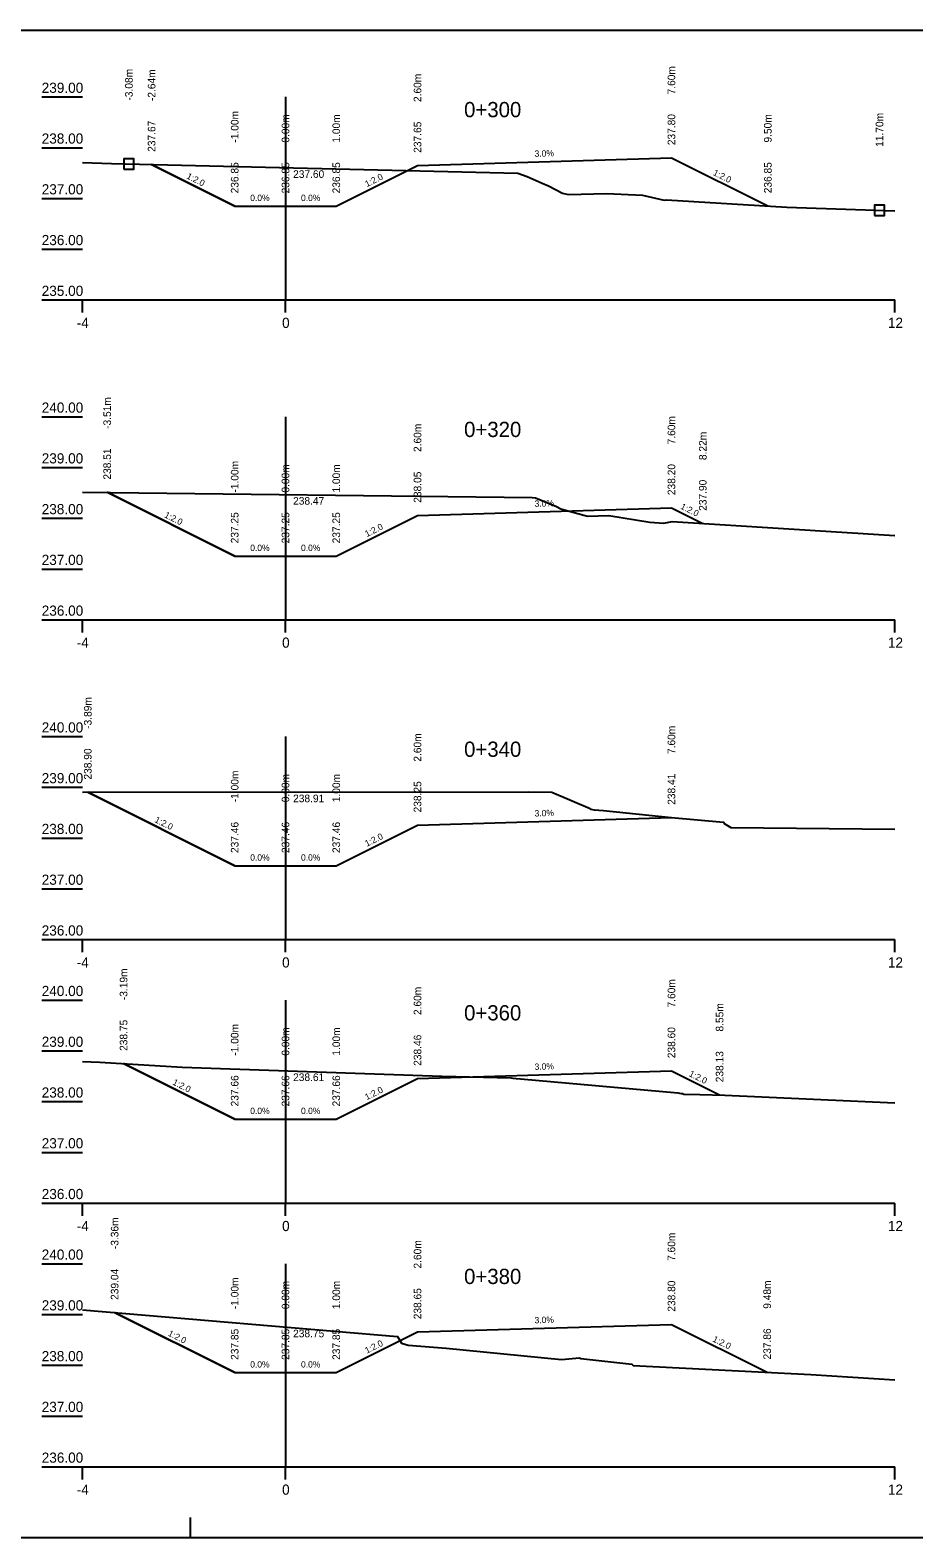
# Model space of a CAD drawing. Extents: x -578374 to -578229, y -1159997 to -1159967.
# Drawn here: x -578295.08 to -578277.68, y -1159996.88 to -1159967.18 of the extents above; entities that cross this region are included whole.
import ezdxf

# ---------------------------------------------------------------- set-up
doc = ezdxf.new("R2010")
doc.units = 0
for name, color, linetype in [('16', 7, 'Continuous'), ('21', 7, 'Continuous'), ('28', 7, 'Continuous'), ('59', 7, 'Continuous'), ('Body pricny rez', 7, 'Continuous'), ('Hranice_pozemku', 7, 'Continuous'), ('Popis pricneho profilu', 7, 'Continuous'), ('Rámy', 7, 'Continuous')]:
    doc.layers.add(name, color=color, linetype=linetype)

msp = doc.modelspace()

# ---------------------------------------------------------------- linework, layer by layer
for points in [[(-578292.693, -1159969.83), (-578291.057, -1159970.649), (-578290.057, -1159970.649), (-578289.057, -1159970.649), (-578287.457, -1159969.849), (-578282.457, -1159969.699), (-578280.559, -1159970.647)], [(-578289.057, -1159970.649), (-578287.457, -1159969.849), (-578282.457, -1159969.699)], [(-578282.457, -1159969.699), (-578280.559, -1159970.647)], [(-578294.057, -1159969.792), (-578293.48, -1159969.812), (-578285.481, -1159970.002), (-578285.299, -1159970.066), (-578285, -1159970.197), (-578284.877, -1159970.247), (-578284.599, -1159970.391), (-578284.489, -1159970.422), (-578283.726, -1159970.398), (-578283.025, -1159970.433), (-578282.599, -1159970.531), (-578282.553, -1159970.523), (-578280.182, -1159970.671), (-578278.057, -1159970.742)], [(-578291.057, -1159970.649), (-578292.693, -1159969.83)], [(-578291.057, -1159970.649), (-578290.057, -1159970.649), (-578289.057, -1159970.649)], [(-578280.559, -1159970.647), (-578280.56, -1159970.647), (-578280.559, -1159970.647), (-578280.56, -1159970.648), (-578280.559, -1159970.647), (-578280.559, -1159970.648), (-578280.559, -1159970.647), (-578280.559, -1159970.647)], [(-578294.057, -1159976.281), (-578285.202, -1159976.389), (-578285.133, -1159976.396), (-578284.72, -1159976.565), (-578284.635, -1159976.61), (-578284.111, -1159976.76), (-578283.69, -1159976.746), (-578282.885, -1159976.873), (-578282.609, -1159976.892), (-578282.444, -1159976.864), (-578278.057, -1159977.137)], [(-578293.568, -1159976.287), (-578291.057, -1159977.543), (-578290.057, -1159977.543), (-578289.057, -1159977.543), (-578287.457, -1159976.743), (-578282.457, -1159976.593), (-578281.84, -1159976.902)], [(-578291.057, -1159977.543), (-578293.568, -1159976.287)], [(-578289.057, -1159977.543), (-578287.457, -1159976.743), (-578282.457, -1159976.593)], [(-578282.457, -1159976.593), (-578281.84, -1159976.902)], [(-578281.84, -1159976.902), (-578281.84, -1159976.901), (-578281.84, -1159976.902), (-578281.84, -1159976.902), (-578281.84, -1159976.902), (-578281.839, -1159976.902), (-578281.84, -1159976.902), (-578281.839, -1159976.901)], [(-578291.057, -1159977.543), (-578290.057, -1159977.543), (-578289.057, -1159977.543)], [(-578294.057, -1159982.197), (-578285.267, -1159982.187), (-578284.821, -1159982.192), (-578284.814, -1159982.192), (-578284.06, -1159982.518), (-578284.049, -1159982.529), (-578283.981, -1159982.545), (-578283.794, -1159982.557), (-578282.457, -1159982.693), (-578281.43, -1159982.784), (-578281.417, -1159982.814), (-578281.289, -1159982.888), (-578278.057, -1159982.921)], [(-578293.95, -1159982.196), (-578291.057, -1159983.643), (-578290.057, -1159983.643), (-578289.057, -1159983.643), (-578287.457, -1159982.843), (-578282.457, -1159982.693)], [(-578291.057, -1159983.643), (-578293.95, -1159982.196)], [(-578289.057, -1159983.643), (-578287.457, -1159982.843), (-578282.457, -1159982.693)], [(-578291.057, -1159983.643), (-578290.057, -1159983.643), (-578289.057, -1159983.643)], [(-578294.057, -1159987.497), (-578293.714, -1159987.512), (-578292.092, -1159987.614), (-578286.979, -1159987.79), (-578285.612, -1159987.822), (-578285.579, -1159987.828), (-578285.512, -1159987.832), (-578285.431, -1159987.838), (-578282.334, -1159988.12), (-578282.267, -1159988.128), (-578282.241, -1159988.128), (-578282.216, -1159988.14), (-578282.215, -1159988.142), (-578282.207, -1159988.146), (-578281.895, -1159988.149), (-578281.404, -1159988.162), (-578278.057, -1159988.317)], [(-578293.245, -1159987.541), (-578291.057, -1159988.635), (-578290.057, -1159988.635), (-578289.057, -1159988.635), (-578287.457, -1159987.835), (-578282.457, -1159987.685), (-578281.509, -1159988.159)], [(-578291.057, -1159988.635), (-578293.245, -1159987.541)], [(-578289.057, -1159988.635), (-578287.457, -1159987.835), (-578282.457, -1159987.685)], [(-578282.457, -1159987.685), (-578281.509, -1159988.159)], [(-578281.509, -1159988.159), (-578281.51, -1159988.159), (-578281.509, -1159988.159), (-578281.51, -1159988.16), (-578281.509, -1159988.159), (-578281.509, -1159988.16), (-578281.509, -1159988.159), (-578281.509, -1159988.159)], [(-578291.057, -1159988.635), (-578290.057, -1159988.635), (-578289.057, -1159988.635)], [(-578294.057, -1159992.392), (-578287.852, -1159992.92), (-578287.771, -1159993.051), (-578287.64, -1159993.086), (-578286.894, -1159993.149), (-578284.619, -1159993.369), (-578284.265, -1159993.339), (-578284.24, -1159993.352), (-578283.234, -1159993.462), (-578283.209, -1159993.489), (-578279.714, -1159993.663), (-578278.057, -1159993.77)], [(-578293.421, -1159992.446), (-578291.057, -1159993.628), (-578290.057, -1159993.628), (-578289.057, -1159993.628), (-578287.457, -1159992.828), (-578282.457, -1159992.678), (-578280.572, -1159993.62)], [(-578291.057, -1159993.628), (-578293.421, -1159992.446)], [(-578289.057, -1159993.628), (-578287.457, -1159992.828), (-578282.457, -1159992.678)], [(-578282.457, -1159992.678), (-578280.572, -1159993.62)], [(-578291.057, -1159993.628), (-578290.057, -1159993.628), (-578289.057, -1159993.628)], [(-578280.572, -1159993.62), (-578280.573, -1159993.62), (-578280.572, -1159993.62), (-578280.573, -1159993.621), (-578280.572, -1159993.62), (-578280.572, -1159993.621), (-578280.572, -1159993.62), (-578280.572, -1159993.62)]]:
    msp.add_lwpolyline(points)
at = {"layer": '16'}
for p, q in [((-578294.057, -1159972.498), (-578278.057, -1159972.498)), ((-578294.057, -1159978.798), (-578278.057, -1159978.798)), ((-578294.057, -1159985.098), (-578278.057, -1159985.098)), ((-578294.057, -1159990.29), (-578278.057, -1159990.29)), ((-578294.057, -1159995.483), (-578278.057, -1159995.483))]:
    msp.add_line(p, q, dxfattribs=at)
at = {"layer": '21'}
for p, q in [((-578294.857, -1159968.498), (-578294.057, -1159968.498)), ((-578294.857, -1159969.498), (-578294.057, -1159969.498)), ((-578294.857, -1159970.498), (-578294.057, -1159970.498)), ((-578294.857, -1159971.498), (-578294.057, -1159971.498)), ((-578294.857, -1159972.498), (-578294.057, -1159972.498)), ((-578294.857, -1159974.798), (-578294.057, -1159974.798)), ((-578294.857, -1159975.798), (-578294.057, -1159975.798)), ((-578294.857, -1159976.798), (-578294.057, -1159976.798)), ((-578294.857, -1159977.798), (-578294.057, -1159977.798)), ((-578294.857, -1159978.798), (-578294.057, -1159978.798)), ((-578294.857, -1159981.098), (-578294.057, -1159981.098)), ((-578294.857, -1159982.098), (-578294.057, -1159982.098)), ((-578294.857, -1159983.098), (-578294.057, -1159983.098)), ((-578294.857, -1159984.098), (-578294.057, -1159984.098)), ((-578294.857, -1159985.098), (-578294.057, -1159985.098)), ((-578294.857, -1159986.29), (-578294.057, -1159986.29)), ((-578294.857, -1159987.29), (-578294.057, -1159987.29)), ((-578294.857, -1159988.29), (-578294.057, -1159988.29)), ((-578294.857, -1159989.29), (-578294.057, -1159989.29)), ((-578294.857, -1159990.29), (-578294.057, -1159990.29)), ((-578294.857, -1159991.483), (-578294.057, -1159991.483)), ((-578294.857, -1159992.483), (-578294.057, -1159992.483)), ((-578294.857, -1159993.483), (-578294.057, -1159993.483)), ((-578294.857, -1159994.483), (-578294.057, -1159994.483)), ((-578294.857, -1159995.483), (-578294.057, -1159995.483))]:
    msp.add_line(p, q, dxfattribs=at)
at = {"layer": '28'}
for p, q in [((-578290.057, -1159968.498), (-578290.057, -1159972.498)), ((-578290.057, -1159974.798), (-578290.057, -1159978.798)), ((-578290.057, -1159981.098), (-578290.057, -1159985.098)), ((-578290.057, -1159986.29), (-578290.057, -1159990.29)), ((-578290.057, -1159991.483), (-578290.057, -1159995.483))]:
    msp.add_line(p, q, dxfattribs=at)
at = {"layer": '59'}
for p, q in [((-578294.057, -1159972.748), (-578294.057, -1159972.498)), ((-578290.057, -1159972.748), (-578290.057, -1159972.498)), ((-578278.057, -1159972.748), (-578278.057, -1159972.498)), ((-578294.057, -1159979.048), (-578294.057, -1159978.798)), ((-578290.057, -1159979.048), (-578290.057, -1159978.798)), ((-578278.057, -1159979.048), (-578278.057, -1159978.798)), ((-578294.057, -1159985.348), (-578294.057, -1159985.098)), ((-578290.057, -1159985.348), (-578290.057, -1159985.098)), ((-578278.057, -1159985.348), (-578278.057, -1159985.098)), ((-578294.057, -1159990.54), (-578294.057, -1159990.29)), ((-578290.057, -1159990.54), (-578290.057, -1159990.29)), ((-578278.057, -1159990.54), (-578278.057, -1159990.29)), ((-578294.057, -1159995.733), (-578294.057, -1159995.483)), ((-578290.057, -1159995.733), (-578290.057, -1159995.483)), ((-578278.057, -1159995.733), (-578278.057, -1159995.483))]:
    msp.add_line(p, q, dxfattribs=at)
at = {"layer": 'Hranice_pozemku'}
for points in [[(-578293.24, -1159969.92), (-578293.04, -1159969.92), (-578293.04, -1159969.72), (-578293.24, -1159969.72)], [(-578278.46, -1159970.832), (-578278.26, -1159970.832), (-578278.26, -1159970.632), (-578278.46, -1159970.632)]]:
    msp.add_lwpolyline(points, close=True, dxfattribs=at)
at = {"layer": 'Rámy'}
msp.add_line((-578291.93, -1159996.883), (-578291.93, -1159996.483), dxfattribs=at)
msp.add_lwpolyline([(-578373.807, -1159967.183), (-578228.93, -1159967.183), (-578228.93, -1159996.883), (-578373.807, -1159996.883)], close=True, dxfattribs=at)

# ---------------------------------------------------------------- texts
for s, height, p in [('0+300', 0.3, (-578286.54, -1159968.898)), ('+', 0.001, (-578290.058, -1159970.649)), ('0+320', 0.3, (-578286.54, -1159975.198)), ('+', 0.001, (-578290.058, -1159977.543)), ('0+340', 0.3, (-578286.54, -1159981.498)), ('+', 0.001, (-578290.058, -1159983.643)), ('0+360', 0.3, (-578286.54, -1159986.69)), ('+', 0.001, (-578290.058, -1159988.636)), ('0+380', 0.3, (-578286.54, -1159991.883)), ('+', 0.001, (-578290.058, -1159993.628))]:
    msp.add_text(s, height=height).set_placement(p)
for rotation, p in [(333.4349, (-578292.017, -1159970.099)), (26.5651, (-578288.455, -1159970.278)), (333.4349, (-578281.65, -1159970.032)), (333.4349, (-578282.29, -1159976.606)), (333.4349, (-578292.454, -1159976.774)), (26.5651, (-578288.455, -1159977.172)), (333.4349, (-578292.645, -1159982.779)), (26.5651, (-578288.455, -1159983.272)), (333.4349, (-578282.125, -1159987.781)), (333.4349, (-578292.293, -1159987.948)), (26.5651, (-578288.455, -1159988.264)), (333.4349, (-578292.381, -1159992.896)), (26.5651, (-578288.455, -1159993.257)), (333.4349, (-578281.657, -1159993.008))]:
    msp.add_text('1:2.0', height=0.125, rotation=rotation).set_placement(p)
at = {"layer": '16'}
for s, rotation, p in [('3.0%', 1.7184, (-578285.151, -1159969.679)), ('0.0%', 360, (-578290.751, -1159970.549)), ('0.0%', 360, (-578289.751, -1159970.549)), ('3.0%', 1.7184, (-578285.151, -1159976.574)), ('0.0%', 360, (-578290.751, -1159977.443)), ('0.0%', 360, (-578289.751, -1159977.443)), ('3.0%', 1.7184, (-578285.151, -1159982.674)), ('0.0%', 360, (-578290.751, -1159983.543)), ('0.0%', 360, (-578289.751, -1159983.543)), ('3.0%', 1.7184, (-578285.151, -1159987.666)), ('0.0%', 360, (-578290.751, -1159988.535)), ('0.0%', 360, (-578289.751, -1159988.535)), ('3.0%', 1.7184, (-578285.151, -1159992.658)), ('0.0%', 360, (-578290.751, -1159993.528)), ('0.0%', 360, (-578289.751, -1159993.528))]:
    msp.add_text(s, height=0.125, rotation=rotation, dxfattribs=at).set_placement(p)
at = {"layer": '21'}
for s, p in [('239.00', (-578294.857, -1159968.418)), ('238.00', (-578294.857, -1159969.418)), ('237.00', (-578294.857, -1159970.418)), ('236.00', (-578294.857, -1159971.418)), ('235.00', (-578294.857, -1159972.418)), ('-4', (-578294.167, -1159973.048)), ('0', (-578290.124, -1159973.048)), ('12', (-578278.195, -1159973.048)), ('240.00', (-578294.857, -1159974.718)), ('239.00', (-578294.857, -1159975.718)), ('238.00', (-578294.857, -1159976.718)), ('237.00', (-578294.857, -1159977.718)), ('236.00', (-578294.857, -1159978.718)), ('-4', (-578294.167, -1159979.348)), ('0', (-578290.124, -1159979.348)), ('12', (-578278.195, -1159979.348)), ('240.00', (-578294.857, -1159981.018)), ('239.00', (-578294.857, -1159982.018)), ('238.00', (-578294.857, -1159983.018)), ('237.00', (-578294.857, -1159984.018)), ('236.00', (-578294.857, -1159985.018)), ('-4', (-578294.167, -1159985.648)), ('0', (-578290.124, -1159985.648)), ('12', (-578278.195, -1159985.648)), ('240.00', (-578294.857, -1159986.21)), ('239.00', (-578294.857, -1159987.21)), ('238.00', (-578294.857, -1159988.21)), ('237.00', (-578294.857, -1159989.21)), ('236.00', (-578294.857, -1159990.21)), ('-4', (-578294.167, -1159990.84)), ('0', (-578290.124, -1159990.84)), ('12', (-578278.195, -1159990.84)), ('240.00', (-578294.857, -1159991.403)), ('239.00', (-578294.857, -1159992.403)), ('238.00', (-578294.857, -1159993.403)), ('237.00', (-578294.857, -1159994.403)), ('236.00', (-578294.857, -1159995.403)), ('-4', (-578294.167, -1159996.033)), ('0', (-578290.124, -1159996.033)), ('12', (-578278.195, -1159996.033))]:
    msp.add_text(s, height=0.2, dxfattribs=at).set_placement(p)
at = {"layer": '59'}
for s, p in [('237.60', (-578289.907, -1159970.093)), ('238.47', (-578289.907, -1159976.53)), ('238.91', (-578289.907, -1159982.392)), ('238.61', (-578289.907, -1159987.884)), ('238.75', (-578289.907, -1159992.932))]:
    msp.add_text(s, height=0.15, dxfattribs=at).set_placement(p)
at = {"layer": 'Body pricny rez'}
for p in [(-578282.458, -1159969.699), (-578292.694, -1159969.831), (-578287.458, -1159969.849), (-578291.058, -1159970.649), (-578289.058, -1159970.649), (-578293.568, -1159976.288), (-578287.458, -1159976.743), (-578282.458, -1159976.593), (-578291.058, -1159977.543), (-578289.058, -1159977.543), (-578293.95, -1159982.197), (-578282.458, -1159982.693), (-578287.458, -1159982.843), (-578291.058, -1159983.643), (-578289.058, -1159983.643), (-578293.245, -1159987.542), (-578287.458, -1159987.836), (-578282.458, -1159987.686), (-578291.058, -1159988.636), (-578289.058, -1159988.636), (-578293.421, -1159992.446), (-578287.458, -1159992.828), (-578282.458, -1159992.678), (-578291.058, -1159993.628), (-578289.058, -1159993.628)]:
    msp.add_text('+', height=0.001, dxfattribs=at).set_placement(p)
at = {"layer": 'Popis pricneho profilu'}
for s, p in [('7.60m', (-578282.382, -1159968.449)), ('-3.08m', (-578293.065, -1159968.57)), ('-2.64m', (-578292.618, -1159968.58)), ('2.60m', (-578287.382, -1159968.599)), ('-1.00m', (-578290.982, -1159969.399)), ('237.80', (-578282.382, -1159969.449)), ('11.70m', (-578278.285, -1159969.482)), ('237.67', (-578292.618, -1159969.58)), ('0.00m', (-578289.982, -1159969.399)), ('1.00m', (-578288.982, -1159969.399)), ('237.65', (-578287.382, -1159969.599)), ('9.50m', (-578280.484, -1159969.397)), ('236.85', (-578290.982, -1159970.399)), ('236.85', (-578289.982, -1159970.399)), ('236.85', (-578288.982, -1159970.399)), ('236.85', (-578280.484, -1159970.397)), ('-3.51m', (-578293.493, -1159975.037)), ('2.60m', (-578287.382, -1159975.493)), ('7.60m', (-578282.382, -1159975.343)), ('8.22m', (-578281.765, -1159975.652)), ('238.51', (-578293.493, -1159976.037)), ('-1.00m', (-578290.982, -1159976.293)), ('0.00m', (-578289.982, -1159976.293)), ('1.00m', (-578288.982, -1159976.293)), ('238.05', (-578287.382, -1159976.493)), ('238.20', (-578282.382, -1159976.343)), ('237.90', (-578281.765, -1159976.652)), ('237.25', (-578290.982, -1159977.293)), ('237.25', (-578289.982, -1159977.293)), ('237.25', (-578288.982, -1159977.293)), ('-3.89m', (-578293.875, -1159980.946)), ('7.60m', (-578282.382, -1159981.443)), ('2.60m', (-578287.382, -1159981.593)), ('238.90', (-578293.875, -1159981.946)), ('-1.00m', (-578290.982, -1159982.393)), ('0.00m', (-578289.982, -1159982.393)), ('1.00m', (-578288.982, -1159982.393)), ('238.41', (-578282.382, -1159982.443)), ('238.25', (-578287.382, -1159982.593)), ('237.46', (-578290.982, -1159983.393)), ('237.46', (-578289.982, -1159983.393)), ('237.46', (-578288.982, -1159983.393)), ('-3.19m', (-578293.17, -1159986.291)), ('2.60m', (-578287.382, -1159986.585)), ('7.60m', (-578282.382, -1159986.435)), ('8.55m', (-578281.434, -1159986.909)), ('238.75', (-578293.17, -1159987.291)), ('-1.00m', (-578290.982, -1159987.385)), ('0.00m', (-578289.982, -1159987.385)), ('1.00m', (-578288.982, -1159987.385)), ('238.60', (-578282.382, -1159987.435)), ('238.46', (-578287.382, -1159987.585)), ('238.13', (-578281.434, -1159987.909)), ('237.66', (-578290.982, -1159988.385)), ('237.66', (-578289.982, -1159988.385)), ('237.66', (-578288.982, -1159988.385)), ('-3.36m', (-578293.346, -1159991.196)), ('2.60m', (-578287.382, -1159991.578)), ('7.60m', (-578282.382, -1159991.428)), ('239.04', (-578293.346, -1159992.196)), ('-1.00m', (-578290.982, -1159992.378)), ('0.00m', (-578289.982, -1159992.378)), ('1.00m', (-578288.982, -1159992.378)), ('238.65', (-578287.382, -1159992.578)), ('238.80', (-578282.382, -1159992.428)), ('9.48m', (-578280.497, -1159992.37)), ('237.85', (-578290.982, -1159993.378)), ('237.85', (-578289.982, -1159993.378)), ('237.85', (-578288.982, -1159993.378)), ('237.86', (-578280.497, -1159993.37))]:
    msp.add_text(s, height=0.15, rotation=90, dxfattribs=at).set_placement(p)

doc.saveas('drawing.dxf')
